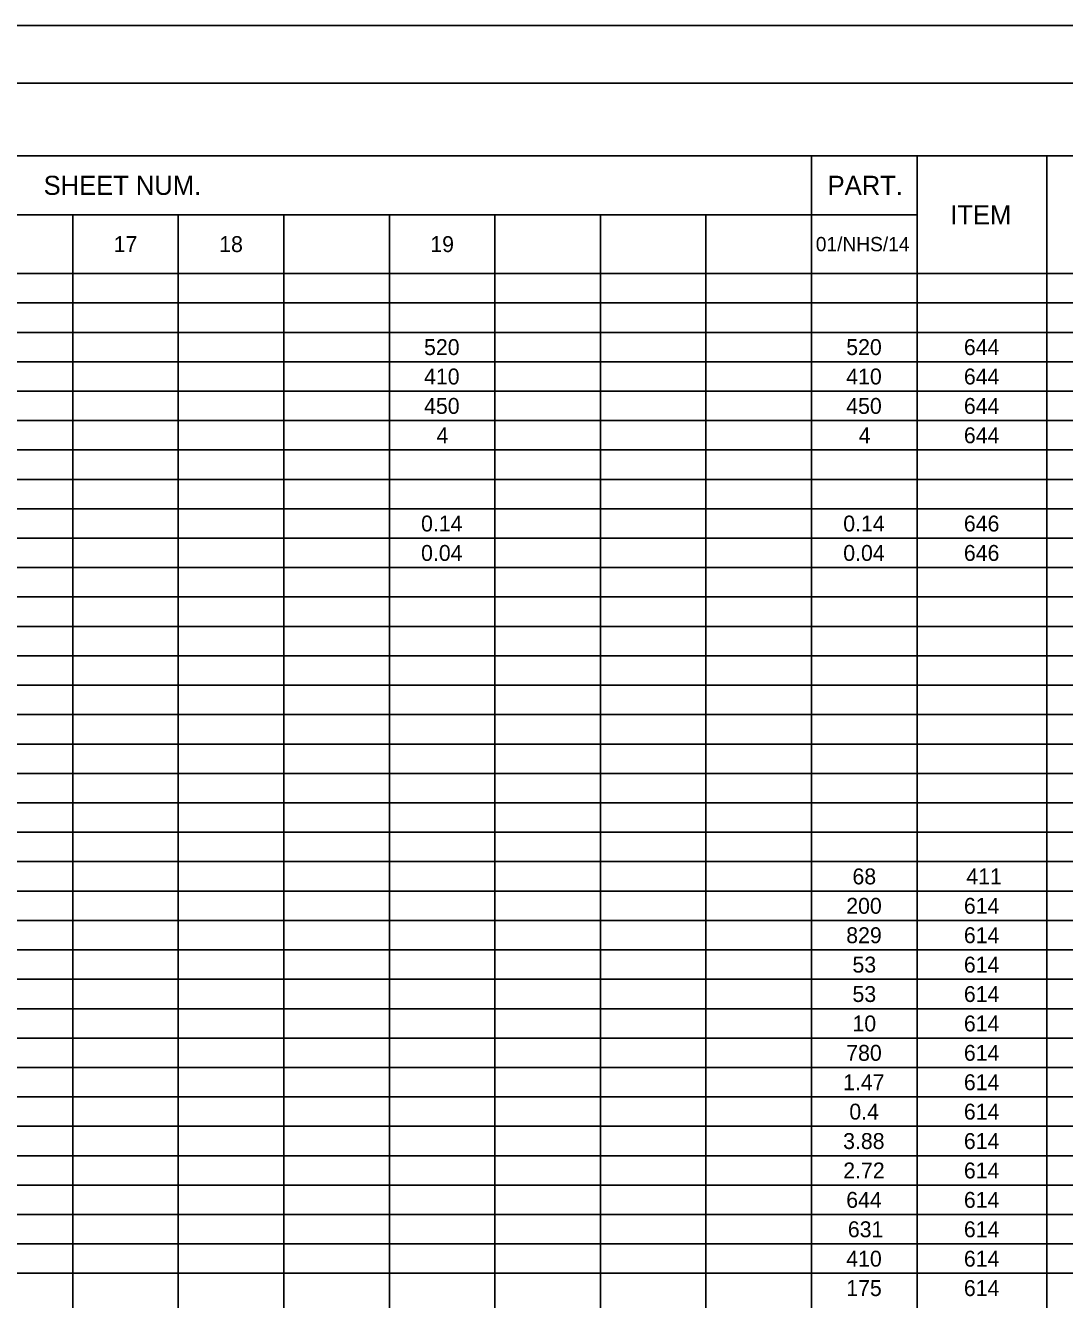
# Model space of a CAD drawing. Extents: x 0 to 34, y 0 to 22.
# Drawn here: x 7.76 to 16.76, y 10.95 to 22 of the extents above; entities that cross this region are included whole.
import ezdxf

# ---------------------------------------------------------------- set-up
doc = ezdxf.new("R2010")
doc.units = 0
for name, color, linetype in [('SH_Border', 7, 'Continuous'), ('SH_Cut_Line', 7, 'Continuous'), ('SH_Text', 7, 'Continuous')]:
    doc.layers.add(name, color=color, linetype=linetype)

msp = doc.modelspace()

# ---------------------------------------------------------------- linework, layer by layer
at = {"layer": 'SH_Border'}
msp.add_lwpolyline([(1.5, 21.5), (33.5, 21.5), (33.5, 0.5), (1.5, 0.5)], close=True, dxfattribs=at)
at = {"layer": 'SH_Cut_Line'}
msp.add_lwpolyline([(0, 0), (34, 0), (34, 22), (0, 22)], close=True, dxfattribs=at)
at = {"layer": 'SH_Text'}
for p, q in [((2.676, 20.869), (30.456, 20.869)), ((14.571, 20.869), (14.571, 1.744)), ((15.486, 20.869), (15.486, 1.744)), ((16.611, 20.869), (16.611, 1.744)), ((2.676, 20.359), (15.486, 20.359)), ((8.166, 20.359), (8.166, 1.744)), ((9.081, 20.359), (9.081, 1.744)), ((9.996, 20.359), (9.996, 1.744)), ((10.911, 20.359), (10.911, 1.744)), ((11.826, 20.359), (11.826, 1.744)), ((12.741, 20.359), (12.741, 1.744)), ((13.656, 20.359), (13.656, 1.744)), ((2.676, 19.849), (30.456, 19.849)), ((2.676, 19.594), (30.456, 19.594)), ((2.676, 19.339), (30.456, 19.339)), ((2.676, 19.084), (30.456, 19.084)), ((2.676, 18.829), (30.456, 18.829)), ((2.676, 18.574), (30.456, 18.574)), ((2.676, 18.319), (30.456, 18.319)), ((2.676, 18.064), (30.456, 18.064)), ((2.676, 17.809), (30.456, 17.809)), ((2.676, 17.554), (30.456, 17.554)), ((2.676, 17.299), (30.456, 17.299)), ((2.676, 17.044), (30.456, 17.044)), ((2.676, 16.789), (30.456, 16.789)), ((2.676, 16.534), (30.456, 16.534)), ((2.676, 16.279), (30.456, 16.279)), ((2.676, 16.024), (30.456, 16.024)), ((2.676, 15.769), (30.456, 15.769)), ((2.676, 15.514), (30.456, 15.514)), ((2.676, 15.259), (30.456, 15.259)), ((2.676, 15.004), (30.456, 15.004)), ((2.676, 14.749), (30.456, 14.749)), ((2.676, 14.494), (30.456, 14.494)), ((2.676, 14.239), (30.456, 14.239)), ((2.676, 13.984), (30.456, 13.984)), ((2.676, 13.729), (30.456, 13.729)), ((2.676, 13.474), (30.456, 13.474)), ((2.676, 13.219), (30.456, 13.219)), ((2.676, 12.964), (30.456, 12.964)), ((2.676, 12.709), (30.456, 12.709)), ((2.676, 12.454), (30.456, 12.454)), ((2.676, 12.199), (30.456, 12.199)), ((2.676, 11.944), (30.456, 11.944)), ((2.676, 11.689), (30.456, 11.689)), ((2.676, 11.434), (30.456, 11.434)), ((2.676, 11.179), (30.456, 11.179))]:
    msp.add_line(p, q, dxfattribs=at)

# ---------------------------------------------------------------- texts
for s, height, p in [('SHEET NUM.', 0.1656, (7.914, 20.531)), ('PART.', 0.1656, (14.711, 20.531)), ('ITEM', 0.1656, (15.774, 20.276)), ('17', 0.138, (8.521, 20.035)), ('18', 0.138, (9.436, 20.035)), ('19', 0.138, (11.266, 20.035)), ('01/NHS/14', 0.1242, (14.608, 20.042)), ('520', 0.138, (11.212, 19.142)), ('520', 0.138, (14.872, 19.142)), ('644', 0.138, (15.892, 19.142)), ('410', 0.138, (11.212, 18.887)), ('410', 0.138, (14.872, 18.887)), ('644', 0.138, (15.892, 18.887)), ('450', 0.138, (11.212, 18.632)), ('450', 0.138, (14.872, 18.632)), ('644', 0.138, (15.892, 18.632)), ('4', 0.138, (11.32, 18.377)), ('4', 0.138, (14.98, 18.377)), ('644', 0.138, (15.892, 18.377)), ('0.14', 0.138, (11.186, 17.612)), ('0.14', 0.138, (14.846, 17.612)), ('646', 0.138, (15.892, 17.612)), ('0.04', 0.138, (11.186, 17.357)), ('0.04', 0.138, (14.846, 17.357)), ('646', 0.138, (15.892, 17.357)), ('68', 0.138, (14.926, 14.552)), ('411', 0.138, (15.913, 14.552)), ('200', 0.138, (14.872, 14.297)), ('614', 0.138, (15.892, 14.297)), ('829', 0.138, (14.872, 14.042)), ('614', 0.138, (15.892, 14.042)), ('53', 0.138, (14.926, 13.787)), ('614', 0.138, (15.892, 13.787)), ('53', 0.138, (14.926, 13.532)), ('614', 0.138, (15.892, 13.532)), ('10', 0.138, (14.926, 13.277)), ('614', 0.138, (15.892, 13.277)), ('780', 0.138, (14.872, 13.022)), ('614', 0.138, (15.892, 13.022)), ('1.47', 0.138, (14.845, 12.767)), ('614', 0.138, (15.892, 12.767)), ('0.4', 0.138, (14.899, 12.512)), ('614', 0.138, (15.892, 12.512)), ('3.88', 0.138, (14.845, 12.257)), ('614', 0.138, (15.892, 12.257)), ('2.72', 0.138, (14.846, 12.002)), ('614', 0.138, (15.892, 12.002)), ('644', 0.138, (14.872, 11.747)), ('614', 0.138, (15.892, 11.747)), ('631', 0.138, (14.886, 11.492)), ('614', 0.138, (15.892, 11.492)), ('410', 0.138, (14.872, 11.237)), ('614', 0.138, (15.892, 11.237)), ('175', 0.138, (14.872, 10.982)), ('614', 0.138, (15.892, 10.982))]:
    msp.add_text(s, height=height, dxfattribs=at).set_placement(p)

doc.saveas('drawing.dxf')
